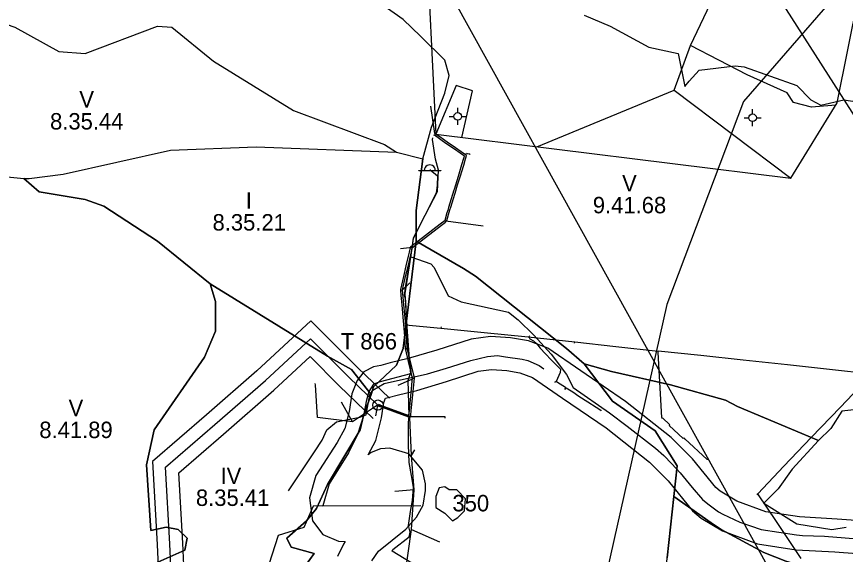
# Model space of a CAD drawing. Extents: x -694504 to -690518, y -983661 to -978958.
# Drawn here: x -692133 to -691377, y -981074 to -980583 of the extents above; entities that cross this region are included whole.
import ezdxf

# ---------------------------------------------------------------- set-up
doc = ezdxf.new("R2010")
doc.units = 0
for name, color, linetype in [('BPEJ', 7, 'Continuous'), ('kabelové a venkovní rozvody telefonu', 7, 'Continuous'), ('ochranné pásmo dálkového kabelu', 7, 'Continuous'), ('ochranné pásmo radioreleové trasy', 7, 'Continuous'), ('ochranné pásmo silnic', 7, 'Continuous'), ('ochranné pásmo vedení', 7, 'Continuous'), ('OP vodního zdroje 1 stupně', 7, 'Continuous'), ('OP vodního zdroje 2 stupně', 7, 'Continuous'), ('trafostanice', 7, 'Continuous'), ('třídy přednosti v ochraně ZP', 7, 'Continuous'), ('vedení NN', 7, 'Continuous'), ('vedení VN 35kV', 7, 'Continuous'), ('vodní zdroj', 7, 'Continuous'), ('vodojem', 7, 'Continuous'), ('vodovodní řad', 7, 'Continuous')]:
    doc.layers.add(name, color=color, linetype=linetype)

msp = doc.modelspace()

# ---------------------------------------------------------------- linework, layer by layer
at = {"layer": 'BPEJ'}
for points in [[(-691369.4, -980941.81), (-691380.4, -980942.81), (-691390.4, -980958.81), (-691401.4, -980969.81), (-691475.4, -980938.81), (-691486.4, -980932.81), (-691536.4, -980918.81), (-691590.4, -980906.81), (-691615.4, -980899.81), (-691631.4, -980885.81), (-691714.4, -980819.81), (-691725.4, -980812.81), (-691768.4, -980787.81), (-691768.4, -980759.81), (-691762.4, -980712.81), (-691754.4, -980683.81), (-691742.4, -980652.81), (-691738.4, -980636.81), (-691742.4, -980622.81), (-691764.4, -980600.81), (-691780.4, -980585.81), (-691822.4, -980555.81)], [(-692231.4, -980700.81), (-692219.4, -980687.81), (-692212.4, -980671.81), (-692214.4, -980642.81), (-692212.4, -980619.81), (-692169.4, -980585.81), (-692160.4, -980583.81), (-692134.4, -980592.81), (-692094.4, -980614.81), (-692070.4, -980616.81), (-692004.4, -980591.81), (-691991.4, -980592.81), (-691953.4, -980623.81), (-691880.4, -980668.81), (-691797.4, -980699.81), (-691786.4, -980706.81)], [(-691615.4, -980581.81), (-691591.4, -980591.81), (-691556.4, -980610.81), (-691529.4, -980616.81), (-691523.4, -980646.81), (-691519.4, -980641.81), (-691510.4, -980631.81), (-691477.4, -980627.81), (-691469.4, -980628.81), (-691421.4, -980645.81), (-691408.4, -980658.81), (-691399.4, -980663.81), (-691378.4, -980658.81), (-691366.4, -980660.81)], [(-692144.4, -980728.81), (-692126.4, -980730.81), (-692112.4, -980742.81), (-692070.4, -980749.81), (-692053.4, -980755.81), (-692004.4, -980787.81), (-691956.4, -980826.81), (-691951.4, -980842.81), (-691951.4, -980869.81), (-691961.4, -980893.81), (-692007.4, -980959.81), (-692014.4, -980991.81), (-692010.4, -981051.81), (-691996.4, -981048.81), (-691985.4, -981050.81), (-691977.4, -981058.81), (-691979.4, -981069.81), (-692042.4, -981097.81)], [(-691862.4, -981144.81), (-691898.4, -981121.81), (-691900.4, -981114.81), (-691896.4, -981104.81), (-691869.4, -981083.81), (-691861.4, -981072.81), (-691882.4, -981066.81), (-691886.4, -981058.81), (-691868.4, -981042.81), (-691859.4, -981031.81), (-691849.4, -981009.81), (-691819.4, -980959.81), (-691816.4, -980946.81), (-691809.4, -980927.81), (-691807.4, -980920.81), (-691786.4, -980900.81), (-691780.4, -980885.81), (-691768.4, -980787.81), (-691725.4, -980812.81), (-691714.4, -980819.81), (-691631.4, -980885.81), (-691615.4, -980899.81), (-691615.4, -980899.81)], [(-692042.4, -981097.81), (-691979.4, -981069.81), (-691977.4, -981058.81), (-691985.4, -981050.81), (-691996.4, -981048.81), (-692010.4, -981051.81), (-692014.4, -980991.81), (-692007.4, -980959.81), (-691961.4, -980893.81), (-691951.4, -980869.81), (-691951.4, -980842.81), (-691956.4, -980826.81), (-691849.4, -980892.81), (-691827.4, -980904.81), (-691809.4, -980927.81), (-691809.4, -980927.81), (-691816.4, -980946.81), (-691819.4, -980959.81), (-691849.4, -981009.81), (-691859.4, -981031.81), (-691868.4, -981042.81), (-691886.4, -981058.81), (-691882.4, -981066.81), (-691861.4, -981072.81), (-691869.4, -981083.81)], [(-691615.4, -980899.81), (-691589.4, -980933.81), (-691550.4, -980960.81), (-691530.4, -980992.81), (-691533.4, -981020.81), (-691539.4, -981076.81)], [(-691323.4, -981103.81), (-691388.4, -981092.81), (-691431.4, -981079.81), (-691451.4, -981071.81), (-691490.4, -981050.81), (-691499.4, -981044.81), (-691533.4, -981020.81), (-691530.4, -980992.81), (-691550.4, -980960.81), (-691589.4, -980933.81), (-691615.4, -980899.81), (-691590.4, -980906.81), (-691536.4, -980918.81), (-691486.4, -980932.81), (-691475.4, -980938.81), (-691401.4, -980969.81), (-691425.4, -980995.81), (-691438.4, -981013.81), (-691451.4, -981026.81), (-691421.4, -981045.81), (-691389.4, -981050.81), (-691376.4, -981048.81)], [(-691363.4, -981277.81), (-691447.4, -981257.81), (-691486.4, -981239.81), (-691504.4, -981221.81), (-691528.4, -981179.81), (-691548.4, -981125.81), (-691542.4, -981112.81), (-691539.4, -981076.81), (-691533.4, -981020.81), (-691499.4, -981044.81), (-691490.4, -981050.81), (-691451.4, -981071.81), (-691431.4, -981079.81), (-691388.4, -981092.81), (-691323.4, -981103.81)]]:
    msp.add_lwpolyline(points, dxfattribs=at)
for points in [[(-691786.4, -980706.81), (-691762.4, -980712.81), (-691768.4, -980759.81), (-691768.4, -980787.81), (-691780.4, -980885.81), (-691786.4, -980900.81), (-691807.4, -980920.81), (-691809.4, -980927.81), (-691827.4, -980904.81), (-691849.4, -980892.81), (-691956.4, -980826.81), (-692004.4, -980787.81), (-692053.4, -980755.81), (-692070.4, -980749.81), (-692112.4, -980742.81), (-692126.4, -980730.81), (-692121.4, -980730.81), (-692090.4, -980726.81), (-691992.4, -980704.81), (-691914.4, -980701.81), (-691786.4, -980706.81)], [(-691742.4, -981011.81), (-691747.4, -981012.81), (-691750.4, -981020.81), (-691750.4, -981030.81), (-691742.4, -981035.81), (-691735.4, -981042.81), (-691730.4, -981039.81), (-691724.4, -981033.81), (-691723.4, -981022.81), (-691731.4, -981014.81), (-691738.4, -981014.81), (-691742.4, -981011.81)]]:
    msp.add_lwpolyline(points, close=True, dxfattribs=at)
at = {"layer": 'kabelové a venkovní rozvody telefonu'}
for points in [[(-691766.8, -981084.99), (-691790.45, -981070.56), (-691789.8, -981069.03), (-691774.82, -981057.63), (-691773.88, -981053.24), (-691775.34, -981047.07), (-691773.6, -981034.28), (-691771.84, -981024.3), (-691770.96, -981012.59), (-691772.73, -981001.69), (-691774.77, -980989.71), (-691775.35, -980973.64), (-691775.35, -980953.17), (-691774.77, -980947.59), (-691775.07, -980936.11), (-691775.64, -980914.64), (-691772.99, -980906.84), (-691775.06, -980892.09), (-691776.52, -980873.07), (-691777.4, -980859.6), (-691777.98, -980841.98), (-691779.14, -980837.04), (-691777.99, -980828.35), (-691773.19, -980802.08), (-691770.96, -980785.43), (-691763.99, -980771.23), (-691749.03, -980742.48), (-691748.15, -980723.25), (-691750.79, -980712.94), (-691753.71, -980695.18), (-691753.41, -980693.58)], [(-691773.19, -980802.08), (-691755.12, -980808.68), (-691751.9, -980811.9), (-691739.31, -980837.68), (-691727.3, -980843.25), (-691684.35, -980852.56), (-691675.57, -980859.59), (-691661.22, -980873.66), (-691645.4, -980890.94), (-691631.35, -980909.4), (-691625.14, -980921.44), (-691592.12, -980944.33), (-691576.01, -980956.64), (-691550.33, -980976.71), (-691542.69, -980983.47), (-691535.35, -980991.1), (-691527.72, -980999.03), (-691516.88, -981012.52), (-691507.25, -981023.61), (-691502.61, -981027.38), (-691492.68, -981034.69), (-691488.92, -981037.01), (-691473.15, -981044.02), (-691453.78, -981050.9), (-691421.73, -981055.63), (-691416.08, -981056.46), (-691396.19, -981057.04), (-691358.4, -981059.97)], [(-691884.89, -981015.52), (-691861.16, -980980.02), (-691854.11, -980969.48), (-691850.09, -980959.99), (-691841.2, -980952.54), (-691819.91, -980948.45), (-691814.04, -980946.29), (-691810.79, -980927.94), (-691807.98, -980923.73), (-691797.6, -980917.67), (-691758.22, -980908.95), (-691740.92, -980903.67), (-691718.69, -980896.64), (-691703.51, -980893.14), (-691694.23, -980892.27), (-691686.97, -980893.43), (-691671.76, -980895.48), (-691666.56, -980896.64), (-691656.4, -980901.28), (-691652.12, -980904.2)]]:
    msp.add_lwpolyline(points, dxfattribs=at)
at = {"layer": 'ochranné pásmo dálkového kabelu'}
msp.add_lwpolyline([(-691386.18, -980026.89), (-691386.18, -980026.89), (-691386.18, -980026.89), (-691386.18, -980026.89), (-691374.89, -980105.48), (-691346.89, -980518.48), (-691469.89, -980660.48), (-691539.89, -980845.48), (-691610.89, -981162.48), (-691809.89, -981375.48), (-691969.89, -981494.48), (-692021.89, -981584.48), (-692040.89, -981697.48), (-692016.89, -981835.48), (-692032.89, -981838.48)], dxfattribs=at)
at = {"layer": 'ochranné pásmo radioreleové trasy'}
for p, q in [((-692444.85, -978981.75), (-690710.16, -981709.99)), ((-692605.8, -978994.48), (-690996.63, -981898.89))]:
    msp.add_line(p, q, dxfattribs=at)
at = {"layer": 'ochranné pásmo silnic'}
for points in [[(-691317.01, -981046.34), (-691384.65, -981041.32), (-691418.89, -981039.42), (-691449.51, -981034.86), (-691476.01, -981024.94), (-691491.2, -981015.87), (-691495.19, -981012.64), (-691516.33, -980986.47), (-691535.81, -980966.85), (-691577.52, -980934.02), (-691618.15, -980906.15), (-691648.37, -980885.55), (-691665.94, -980878.86), (-691682.33, -980876.03), (-691700.69, -980874.86), (-691718.44, -980877.15), (-691749.63, -980887.19), (-691775.72, -980895.01), (-691792.05, -980898.84), (-691800.57, -980901.18), (-691807.23, -980902.38), (-691816.26, -980907.17), (-691822.23, -980914.84), (-691827.14, -980927.04), (-691829.63, -980943.33), (-691833.38, -980958.79), (-691840.4, -980971.51), (-691859.86, -981001.51), (-691865.88, -981021.99), (-691863.13, -981042.82), (-691853.44, -981055.32), (-691839.35, -981061.58), (-691833.15, -981061.92), (-691834.8, -981064.21), (-691840.31, -981075.51)], [(-691808.91, -981079.56), (-691802.68, -981070.76), (-691777.97, -981050.69), (-691768.12, -981039.71), (-691762.2, -981028.66), (-691760.08, -981015.2), (-691760.08, -981009.06), (-691762.55, -980996.71), (-691775.16, -980981.84), (-691792.52, -980976.69), (-691801.08, -980977.33), (-691809.56, -980980.76), (-691812.26, -980982.63), (-691805.18, -980969.77), (-691800.17, -980949.14), (-691798.01, -980935.02), (-691796.37, -980930.92), (-691793.92, -980930.47), (-691784.65, -980927.91), (-691767.99, -980924.01), (-691740.73, -980915.84), (-691711.86, -980906.55), (-691699.71, -980904.98), (-691685.85, -980905.87), (-691673.9, -980907.93), (-691662.34, -980912.33), (-691635.08, -980930.91), (-691595.3, -980958.2), (-691555.81, -980989.29), (-691538.7, -981006.52), (-691516.53, -981033.97), (-691508.41, -981040.53), (-691489.06, -981052.08), (-691457.06, -981064.07), (-691421.94, -981069.3), (-691386.59, -981071.26), (-691318.66, -981076.3)]]:
    msp.add_lwpolyline(points, dxfattribs=at)
at = {"layer": 'ochranné pásmo vedení'}
for points in [[(-691792.72, -980931.21), (-691822.1, -980903.17), (-691864.46, -980860.54), (-691913.85, -980906.25), (-691959.7, -980946.13), (-692009.06, -980988.9), (-692004.73, -981064.6), (-692001.73, -981131.67), (-691997.92, -981186.06), (-692018.89, -981236.58), (-692039.93, -981289.69), (-692056.39, -981331.65), (-692131.85, -981317.45), (-692234.86, -981298.45), (-692432.9, -981261.44), (-692500.89, -981249.44), (-692585.86, -981233.45), (-692655.55, -981220.75), (-692739.96, -981204.97), (-692834.02, -981187.35)], [(-691558.97, -981380.3), (-691573.82, -981399.76), (-691582.36, -981410.87), (-691889.01, -981360.42), (-691967.02, -981346.42), (-692032.75, -981335.74), (-692018.07, -981298.31), (-691997.11, -981245.42), (-691974.08, -981189.94), (-691978.27, -981130.33), (-691981.27, -981063.4), (-691984.94, -980999.1), (-691944.3, -980963.87), (-691898.15, -980923.75), (-691865.14, -980893.19), (-691838.56, -980919.95), (-691807.63, -980949.47)]]:
    msp.add_lwpolyline(points, dxfattribs=at)
at = {"layer": 'OP vodního zdroje 1 stupně'}
msp.add_lwpolyline([(-691726.96, -980693.28), (-691717.2, -980650.89), (-691731.93, -980645.81), (-691750.53, -980690.37)], dxfattribs=at)
at = {"layer": 'OP vodního zdroje 2 stupně'}
msp.add_line((-691533.02, -980650.11), (-691426.68, -980730.35), dxfattribs=at)
msp.add_lwpolyline([(-691584.7, -979993.09), (-691645.48, -980041.57), (-691739.76, -980384.58), (-691760.06, -980498.36), (-691750.53, -980690.37), (-691426.68, -980730.35), (-691384.54, -980661.78), (-691268.79, -980085.77), (-691256.85, -980025.58)], close=True, dxfattribs=at)
for points in [[(-691658.52, -980701.73), (-691533.02, -980650.11), (-691518.3, -980609.48), (-691500.17, -980571.22), (-691507.13, -980538.12), (-691757.63, -980484.74)], [(-691385.71, -980663.69), (-691407.77, -980665.7), (-691424.36, -980661.36), (-691430.11, -980652.49), (-691466.66, -980636.24), (-691518.3, -980609.48)]]:
    msp.add_lwpolyline(points, dxfattribs=at)
at = {"layer": 'trafostanice'}
msp.add_ellipse((-691803.29, -980937.37), major_axis=(0, 4.66), ratio=0.997816, dxfattribs=at)
at = {"layer": 'vedení NN'}
for points in [[(-691751.35, -980689.74), (-691755.16, -980664.73)], [(-691801.42, -980938.08), (-691801.08, -980937.36), (-691802.67, -980936.76), (-691800.88, -980937.4), (-691797.78, -980938.53), (-691784.42, -980943.39), (-691775.12, -980946.76), (-691775.1, -980946.55), (-691774.66, -980942.2), (-691773.02, -980925.85), (-691772, -980915.68), (-691771.71, -980912.84), (-691771.71, -980912.84), (-691771.71, -980912.79), (-691771.97, -980911.75), (-691775.37, -980897.61), (-691778.2, -980885.79), (-691778.21, -980885.73), (-691778.93, -980874.92), (-691779.68, -980863.83), (-691779.69, -980863.69), (-691779.93, -980860.96), (-691781.27, -980845.93), (-691782.03, -980837.44), (-691782.48, -980832.15), (-691782.49, -980832.08), (-691779.67, -980819.97), (-691777.47, -980810.48), (-691775.39, -980801.53), (-691774.55, -980797.91), (-691773.35, -980792.72), (-691773.34, -980792.68), (-691773.32, -980792.6), (-691746.51, -980772.14), (-691742.17, -980768.84), (-691742.17, -980768.84), (-691740.05, -980761.82), (-691739.3, -980759.32), (-691739.09, -980758.63), (-691738.56, -980756.86), (-691733.74, -980740.92), (-691733.62, -980740.52), (-691729.91, -980728.47), (-691726.71, -980718.06), (-691724.91, -980712.24), (-691724.36, -980710.41), (-691724.36, -980710.41), (-691724.36, -980710.4), (-691728.27, -980707.67), (-691733.46, -980704.06), (-691741.31, -980698.66), (-691751.87, -980691.3), (-691752.21, -980691.04), (-691752.48, -980691.44)], [(-691723.19, -980709.24), (-691723.51, -980709.01), (-691727.54, -980706.24), (-691732.53, -980702.77), (-691740.1, -980697.54), (-691746.87, -980692.83), (-691750.75, -980690.14), (-691751.35, -980689.74)], [(-691723.19, -980709.24), (-691722.69, -980707.68)], [(-691722.69, -980707.68), (-691721.9, -980707.89), (-691719.67, -980708.32), (-691719.68, -980708.57), (-691719.28, -980708.59)], [(-691732.1, -980741.03), (-691732.04, -980740.83), (-691730.67, -980736.35), (-691728.44, -980729.16), (-691725.13, -980718.42), (-691723.36, -980712.65), (-691723.16, -980711.99), (-691722.47, -980709.75), (-691723.19, -980709.24)], [(-691741.48, -980769.32), (-691740.58, -980769.11), (-691737.64, -980759.36), (-691736.83, -980756.75), (-691732.1, -980741.03)], [(-691771.89, -980793.52), (-691745.22, -980773.23), (-691741.65, -980770.44), (-691741.48, -980769.32)], [(-691741.49, -980770.58), (-691741.48, -980769.32)], [(-691741.48, -980769.32), (-691707.26, -980773.83)], [(-691771.89, -980793.52), (-691782.87, -980794.71)], [(-691780.87, -980832.2), (-691778.07, -980820.15), (-691775.9, -980810.82), (-691771.89, -980793.52)], [(-691780.87, -980832.2), (-691774.16, -980825.9)], [(-691781.58, -980833.4), (-691780.87, -980832.2)], [(-691776.37, -980864.05), (-691776.35, -980863.84), (-691778.08, -980863.7), (-691778.33, -980860.87), (-691779.67, -980845.84), (-691780.27, -980839.01), (-691780.87, -980832.2)], [(-691778.07, -980864.11), (-691776.39, -980864.25), (-691776.37, -980864.05)], [(-691778.07, -980864.11), (-691745.86, -980867.35)], [(-691776.54, -980885.77), (-691776.68, -980884.49), (-691777.37, -980874.37), (-691778.07, -980864.11)], [(-691745.74, -980866.11), (-691745.86, -980867.35)], [(-691745.86, -980867.35), (-691706.36, -980871.17), (-691666.23, -980875.25)], [(-691666.23, -980875.25), (-691623.78, -980879.68)], [(-691665.36, -980874.31), (-691665.22, -980874.47), (-691665.79, -980875.22), (-691664.7, -980876.8), (-691661.48, -980878.68), (-691658.83, -980881.28), (-691655.36, -980885.45), (-691650.49, -980890.74), (-691645.33, -980896.1), (-691640.79, -980900.62), (-691636.85, -980904.74), (-691637.05, -980907.64), (-691640.74, -980915.74), (-691642, -980916.59), (-691640.49, -980915.91), (-691637.01, -980918.01), (-691632.17, -980921.17), (-691632, -980921.29), (-691633.02, -980922.67), (-691632.86, -980922.79)], [(-691623.93, -980880.91), (-691623.78, -980879.68)], [(-691623.78, -980879.68), (-691586.27, -980883.9), (-691547.69, -980888.12)], [(-691778.67, -980885.74), (-691776.54, -980885.77)], [(-691770.07, -980912.84), (-691770.44, -980911.27), (-691773.71, -980897.72), (-691776.54, -980885.77)], [(-691547.81, -980889.35), (-691547.69, -980888.12)], [(-691352.9, -980910.43), (-691352.84, -980909.18), (-691391.61, -980904.86), (-691429.78, -980900.78), (-691470.1, -980896.55), (-691508.95, -980892.24), (-691547.69, -980888.12)], [(-691544.25, -980949.29), (-691544.41, -980949.15), (-691544.12, -980948.82), (-691544.37, -980948.59), (-691547.81, -980889.35)], [(-691456.74, -981018.2), (-691433.23, -980992.97), (-691408.25, -980967), (-691381.38, -980939.4), (-691353.26, -980909.52), (-691353.3, -980910.42), (-691352.9, -980910.43)], [(-691858.44, -980948.77), (-691860.42, -980918.85), (-691860.59, -980917.59)], [(-691770.07, -980912.84), (-691785.3, -980919.37)], [(-691774.42, -980947.87), (-691773.61, -980948.08), (-691773.48, -980946.55), (-691773.06, -980942.3), (-691771.92, -980930.92), (-691770.07, -980912.84)], [(-691632.86, -980922.79), (-691632.7, -980922.91), (-691631.68, -980921.53), (-691631.54, -980921.61), (-691625.62, -980925.35), (-691620.14, -980929.11), (-691611.97, -980934.35), (-691604.29, -980939.41), (-691600.11, -980941.96), (-691599.6, -980942.6)], [(-691826.52, -980952.6), (-691836.7, -980934.7)], [(-691803.83, -980937.58), (-691826.52, -980952.6)], [(-691803.83, -980937.58), (-691805.5, -980947.14)], [(-691801.42, -980938.08), (-691801.59, -980938.45), (-691803.83, -980937.58)], [(-691801.42, -980938.08), (-691801.75, -980938.82), (-691803.56, -980938.12)], [(-691772.84, -980983.33), (-691774.38, -980948.72), (-691774.38, -980948.72), (-691775.23, -980948.43), (-691781.7, -980946.08), (-691795.96, -980940.87), (-691803.56, -980938.12)], [(-691774.42, -980947.87), (-691802.74, -980937.56)], [(-691801.42, -980938.08), (-691802.74, -980937.56)], [(-691826.52, -980952.6), (-691858.44, -980948.77)], [(-691774.42, -980947.87), (-691742.37, -980947.92), (-691742.34, -980949.2)], [(-691544.25, -980949.29), (-691544.1, -980949.43), (-691543.82, -980949.09), (-691537.23, -980955.29), (-691537.87, -980956.02), (-691524.92, -980967.77), (-691524.4, -980967.22), (-691523.69, -980967.88), (-691523.87, -980968.08), (-691523.73, -980968.21)], [(-691523.73, -980968.21), (-691523.58, -980968.34), (-691523.38, -980968.12), (-691502.96, -980986.91), (-691503.21, -980987.17)], [(-691772.84, -980983.33), (-691769.71, -980978.12)], [(-691770.2, -981014.74), (-691772.84, -980983.33)], [(-691770.2, -981014.74), (-691788.05, -981016.27)], [(-691772.72, -981050.74), (-691770.2, -981014.74)], [(-691457.58, -981019.14), (-691456.74, -981018.2)], [(-691417.31, -981077.3), (-691439.8, -981043.48), (-691456.74, -981018.2)], [(-691778.36, -981091.82), (-691772.72, -981050.74)], [(-691772.72, -981050.74), (-691747.25, -981061.96)]]:
    msp.add_lwpolyline(points, dxfattribs=at)
at = {"layer": 'vedení VN 35kV'}
msp.add_lwpolyline([(-692109.51, -981559.46), (-692097, -981517), (-692087, -981479), (-692074, -981432), (-692061, -981387), (-692049, -981345), (-692029, -981294), (-692008, -981241), (-691986, -981188), (-691990, -981131), (-691993, -981064), (-691997, -980994), (-691952, -980955), (-691906, -980915), (-691864.8, -980876.87), (-691830.33, -980911.56), (-691803.29, -980937.37)], dxfattribs=at)
at = {"layer": 'vodní zdroj'}
for p, q in [((-691730.56, -980670.6), (-691730.56, -980666.2)), ((-691461.59, -980671.8), (-691461.59, -980667.4)), ((-691738.39, -980674.03), (-691733.99, -980674.03)), ((-691727.13, -980674.03), (-691722.73, -980674.03)), ((-691469.42, -980675.23), (-691465.02, -980675.23)), ((-691458.16, -980675.23), (-691453.76, -980675.23)), ((-691730.56, -980681.86), (-691730.56, -980677.46)), ((-691461.59, -980683.06), (-691461.59, -980678.66))]:
    msp.add_line(p, q, dxfattribs=at)
for centre in [(-691730.56, -980674.03), (-691461.59, -980675.23)]:
    msp.add_circle(centre, 3.43, dxfattribs=at)
at = {"layer": 'vodojem'}
for p, q in [((-691766.08, -980723.29), (-691761.08, -980723.29)), ((-691766.08, -980723.82), (-691766.08, -980723.29)), ((-691766.08, -980723.82), (-691766.08, -980723.29)), ((-691766.08, -980723.29), (-691761.08, -980723.29)), ((-691745.97, -980723.82), (-691766.08, -980723.82)), ((-691745.97, -980723.82), (-691766.08, -980723.82)), ((-691751.01, -980723.28), (-691745.97, -980723.28)), ((-691751.01, -980723.28), (-691745.97, -980723.28)), ((-691745.97, -980723.28), (-691745.97, -980723.82)), ((-691745.97, -980723.28), (-691745.97, -980723.82))]:
    msp.add_line(p, q, dxfattribs=at)
msp.add_ellipse((-691756.04, -980723.28), major_axis=(-5.03, 0), ratio=0.990986, start_param=3.141359, end_param=6.28742, dxfattribs=at)
msp.add_ellipse((-691756.04, -980723.28), major_axis=(-5.03, 0), ratio=0.990986, start_param=3.141359, end_param=6.28742, dxfattribs=at)
at = {"layer": 'vodovodní řad'}
for points in [[(-691756.03, -980722.45), (-691748.97, -980728.16), (-691749.35, -980737.15), (-691750.1, -980743.9), (-691764.33, -980771.63), (-691771.07, -980785.01), (-691773.32, -980800.75), (-691778.94, -980835.6), (-691778.57, -980840.73), (-691777.07, -980866.21), (-691774.82, -980895.06), (-691773.7, -980908.93), (-691801.41, -980916.05), (-691807.4, -980918.3), (-691811.52, -980925.04), (-691814.15, -980934.03), (-691816.39, -980947.15), (-691822.05, -980964.19), (-691830.2, -980980.78), (-691847.94, -981009.22), (-691853.47, -981029.3), (-691862.48, -981029.59), (-691870.97, -981049.04), (-691894.19, -981056.37), (-691951.24, -981233.09)], [(-691853.47, -981029.3), (-691764.17, -981029.04)]]:
    msp.add_lwpolyline(points, dxfattribs=at)

# ---------------------------------------------------------------- texts
at = {"layer": 'trafostanice'}
msp.add_text('T 866', height=15, dxfattribs=at).set_placement((-691837.23, -980886.66))
at = {"layer": 'třídy přednosti v ochraně ZP'}
for s, p in [('V', (-692075.67, -980666.02)), ('8.35.44', (-692102.36, -980686.02)), ('V', (-691580.67, -980742.45)), ('I', (-691923.87, -980758.18)), ('9.41.68', (-691607.36, -980762.45)), ('8.35.21', (-691954.18, -980778.18)), ('V', (-692085.47, -980947.48)), ('8.41.89', (-692112.16, -980967.48)), ('IV', (-691946.88, -981009.36)), ('8.35.41', (-691969.33, -981029.36)), ('350', (-691735.37, -981034.31))]:
    msp.add_text(s, height=15, dxfattribs=at).set_placement(p)

doc.saveas('drawing.dxf')
